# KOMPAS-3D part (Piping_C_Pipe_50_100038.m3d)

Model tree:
1. Plane XY
2. Plane ZX
3. Plane ZY
4. X Axis
5. Y Axis
6. Z Axis
7. Origin
8. Path  (labels: Отвод 90 Dy 50; Труба Dy 50)
9. Plane of section
10. Section of pipe
11. Pipe
     Толщина стенки 1 = 1

Referenced files in C:\Program Files\ASCON\KOMPAS-3D V10\Libs\Piping\Models\Tanks\: Tanks.a3d
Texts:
  Pipe Dn 50
  Three Point Plane
  Plane at Angle
  Line and Point Plane
  Axis through Two Vertices
  Axis of Feature
  Axis of Conical Surface
  Axis through Edge
  Приклеить элемент выдавливания
  Приклеить элемент вращения
  Приклеить кинематический элемент
  Приклеить элемент по сечениям
  Trim by Surface
  Trim by Sketch
  Feature with No History
  Intersection Axis of Two Planes
  Two Line Plane
  Line and Face Plane
  Bend by line
  Hole in sheet body
  Cut in sheet body
  Point in CM
  Linear Dimension from Line to Point
  Surface Finish Symbol
  Geometric Tolerance Symbol
  Текст на чертеже
  Линия-выноска #1
  Линия-выноска #2
  Линия-выноска #3
  Отклонения формы и база
  Марка координационной оси
  Марка/позиционное обозначение с линией-выноской
  Марка/позиционное обозначение на линии
  Марка/позиционное обозначение без линии-выноски
  Отвод 90 Dy 50
  Труба Dy 50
